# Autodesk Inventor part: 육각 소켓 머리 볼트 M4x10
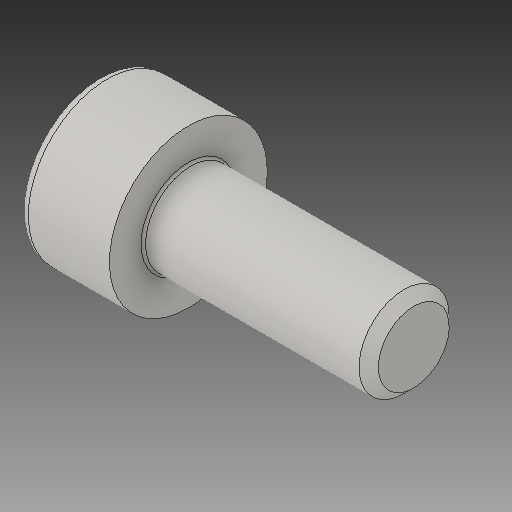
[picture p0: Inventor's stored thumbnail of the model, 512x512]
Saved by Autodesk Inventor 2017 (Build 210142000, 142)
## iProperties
Created: 2024-09
Part Number: 육각 소켓 머리 볼트 M4x10
Material: 일반
Description: 6각머리 태핑 나사
Document SubType Name: Modeling
Designer: MRC
Density: 1 g/cm^3
Appearance: 기본값
Author: jhkim
Sending System: Autodesk Inventor 2025
Preprocessor: ST-DEVELOPER v20
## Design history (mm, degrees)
feature "Solid1"
node "솔리드1"
